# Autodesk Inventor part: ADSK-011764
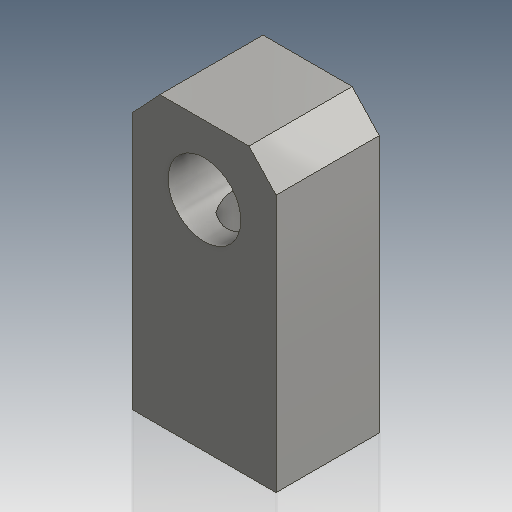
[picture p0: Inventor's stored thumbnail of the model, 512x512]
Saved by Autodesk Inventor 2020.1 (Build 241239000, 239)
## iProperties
Created: 1999-12
Part Number: ADSK-011764
Material: Aluminum
Description: MOUNT,CYLINDER,KNUCKLE,0.500 PIN
Document SubType Name: Modeling
Designer: sspink
Density: 2.71 g/cm^3
Appearance: Steel
Mass: 46.6573 g
Surface Area: 64.0049 cm^2
Volume: 17.2167 cm^3
Control State: 0
Checked Out: False
Last Check In By: sspink
Last Check In Date: 1999-12-16
Master: False
Shininess: 0.0
Length Units: 11269
Angle Units: 11279
Time Units: 11290
Mass Units: 11283
Length Display Precision: 3
Angle Display Precision: 2
Compacted: True
Dimensions: 50x18x25 mm
Mass: 0,047 kg
VLT_Material: Aluminum
Density: 0.0
Volumn: 0.0
Area: 0.0
PropertySet Name: Model Information
Author: sspink
Revision Number: -
Title: MOUNT,CYLINDER,KNUCKLE,0.500 PIN
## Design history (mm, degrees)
node "Solide1"
  node "Extrusion1" dims "d6" = 18, "d7" = 0
  node "Hole1" dims "d8" = 10.106, "d9" = 9.525, "d10" = 6.35, "d11" = 60 deg, "d12" = 32.3, "d13" = 118 deg, "d14" = 24
sketch "Sketch1"
  geometry: L1 (-12.5, -38)-(12.5, -38); L2 (12.5, -38)-(12.5, 12); L3 (12.5, 12)-(-12.5, 12); L4 (-12.5, 12)-(-12.5, -38); L5 (0, -38)-(0, 0); L6 (7.778, 12)-(12.5, 6.946); L7 (-12.5, 6.946)-(-7.778, 12); C1 r 6.35 at (0, 0); A1 r 14.3 centre (0, 0) between (7.778, 12) and (12.5, 6.946); 1 further point
  constraints: 14 end point, 4 point on circle, 4 point on line, 3 parallel, 2 centre point, 2 coincident, 1 horizontal, 1 midpoint, 1 perpendicular
  dimensions: "d0" = 50 distance of L1.end L2.end; "d1" = 25 distance of L1.start L1.end; "d3" = 12.7 diameter of C1; "d4" = 38 distance of L5.start L5.end; "d5" = 28.6004 diameter of A1
workplane "Work Plane1"
node "Corps solides"
node "Corps surfaciques"
sketch "Sketch2"
  geometry: L1 (25, 18)-(0, 18) reference; L2 (0, 0)-(0, 18) reference; L3 (0, 0)-(25, 0) reference; L4 (25, 0)-(25, 18) reference; L5 (0, 9)-(25, 9); L6 (12.5, 18)-(12.5, 0); 1 further point
  constraints: 5 midpoint, 4 end point
